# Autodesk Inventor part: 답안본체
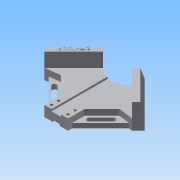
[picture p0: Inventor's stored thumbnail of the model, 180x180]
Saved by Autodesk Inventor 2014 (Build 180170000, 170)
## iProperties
Created: 2020-05
Part Number: 답안본체
Material: 알루미늄 6061
Document SubType Name: Modeling
Designer: NET
Density: 2.71 g/cm^3
Appearance: 알루미늄 - 평지
Mass: 573.609 g
Surface Area: 407.345 cm^2
Volume: 211.664 cm^3
Author: NET
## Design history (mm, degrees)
sketch "스케치1"
  geometry: L1 (0, 169.706)-(-84.853, 84.853); L2 (-84.853, 84.853)-(0, 0); L3 (0, 0)-(84.853, 84.853); L4 (84.853, 84.853)-(0, 169.706); 1 further point
  constraints: 8 end point, 3 perpendicular, 1 coincident, 1 horizontal alignment
  dimensions: "d5" = 120 distance of L3.end L1.start; "d7" = 90 deg angle of L2 L3
extrude "돌출1" new body sketch "스케치1" distance "d8" = 18; taper "d9" = 0 deg
sketch "스케치2"
  geometry: L1 (0, 169.706)-(-84.853, 84.853) reference; L2 (84.853, 84.853)-(0, 169.706) reference; L3 (0, 0)-(0, 20); L4 (-8, 20)-(8, 20); L5 (-8, 20)-(-8, 115); L6 (-8, 115)-(8, 115); L7 (8, 115)-(8, 20); L8 (0, 169.706)-(-23.241, 146.464); L9 (0, 169.706)-(35.355, 134.35); L10 (0, 169.706)-(-35.355, 134.35); L11 (35.355, 134.35)-(16.005, 115); L12 (-35.355, 134.35)-(-16.005, 115); L13 (8, 115)-(16.005, 115); L14 (16.005, 115)-(-8, 115); L15 (-8, 115)-(-16.005, 115)
  constraints: 26 end point, 5 perpendicular, 3 point on line, 2 collinear, 2 vertical, 1 midpoint, 1 parallel
  dimensions: "d11" = 20 distance of L3.end L3.start; "d13" = 16 distance of L4.start L4.end; "d14" = 95 distance of L6.end L4.end; "d15" = 50 distance of L1.start L9.end; "d16" = 50 distance of L1.start L10.end
extrude "돌출2" cut sketch "스케치2" distance "d17" = 18; taper "d18" = 0 deg
extrude "돌출3" cut sketch "스케치2" distance "d19" = 3.5; taper "d20" = 0 deg
sketch "스케치3"
  geometry: L1 (-35.355, 134.35)-(-84.853, 84.853) reference; L2 (-84.853, 84.853)-(0, 0) reference; L3 (0, 0)-(84.853, 84.853) reference; L4 (8, 20)-(-8, 20) reference; L5 (-20, 20)-(20, 20); L6 (-84.853, 84.853)-(-29.096, 29.096); L7 (-70.711, 98.995)-(-14.954, 43.238); L8 (-20, 20)-(-20, 48.284); L9 (-84.853, 84.853)-(-67.035, 102.671); L10 (-56.428, 92.064)-(-74.246, 74.246); L11 (-45.7, 81.579)-(-49.497, 77.782); L12 (-74.246, 74.246)-(-49.497, 77.782)
  constraints: 16 end point, 7 point on line, 1 collinear, 1 parallel, 1 perpendicular
  dimensions: "d21" = 40 distance of L5.start L5.end; "d22" = 20 distance between parallel lines of L6 L7; "d23" = 15 distance between parallel lines of L9 L10; "d24" = 30 distance between parallel lines of L9 L11
extrude "돌출4" cut sketch "스케치3" distance "d25" = 10; taper "d26" = 0 deg
sketch "스케치4"
  geometry: L1 (-20, 20)-(-74.246, 74.246) reference; L2 (-20, 48.284)-(-20, 20) reference; L3 (-74.246, 74.246)-(-20, 20); L4 (-70.711, 77.782)-(-20, 27.071); L5 (-65.761, 82.731)-(-22.641, 39.611); L6 (-35.355, 134.35)-(-84.853, 84.853) reference; L7 (-16.005, 115)-(16.005, 115) reference; L8 (16.005, 115)-(35.355, 134.35) reference; L9 (35.355, 134.35)-(84.853, 84.853) reference; L10 (84.853, 84.853)-(0, 0) reference; L11 (0, 0)-(-20, 20) reference; L12 (-20, 20)-(-20, 48.284) reference; L13 (-20, 48.284)-(-49.497, 77.782) reference; L14 (-49.497, 77.782)-(-74.246, 74.246) reference; L15 (-20, 20)-(-74.246, 74.246) reference; L16 (-35.355, 134.35)-(-16.005, 115) reference; L17 (-84.853, 84.853)-(-35.355, 134.35) reference; L18 (-74.246, 74.246)-(-84.853, 84.853) reference; L19 (-67.244, 102.462)-(-84.853, 84.853); L20 (-61.193, 87.299)-(-74.246, 74.246); L21 (-37.371, 78.594)-(-54.447, 61.518); L22 (-26.87, 49.497)-(-46.669, 69.296); L23 (-32.527, 43.841)-(-52.326, 63.64); L24 (-74.246, 74.246)-(-49.497, 77.782) reference; L25 (-74.246, 74.246)-(-68.059, 75.13); L26 (-20, 27.071)-(-20, 20); A1 r 4 centre (-49.497, 66.468) between (-46.669, 69.296) and (-52.326, 63.64); A2 r 4 centre (-29.698, 46.669) between (-32.527, 43.841) and (-26.87, 49.497)
  constraints: 20 end point, 11 point on line, 4 point on circle, 3 parallel, 3 perpendicular, 2 centre point, 2 collinear
  dimensions: "d27" = 5 distance between parallel lines of L1 L4; "d28" = 12 distance between parallel lines of L1 L5; "d29" = 15 distance between parallel lines of L19 L20; "d30" = 38 distance between parallel lines of L19 L21; "d31" = 4 radius of A1; "d32" = 4 radius of A2; "d33" = 28 distance of L23.start L23.end
  node "절단 모서리 투영1"
extrude "돌출5" cut sketch "스케치4" distance "d34" = 10; taper "d35" = 0 deg
extrude "돌출6" cut sketch "스케치4" distance "d36" = 10; taper "d37" = 0 deg
sketch "스케치5"
  geometry: L1 (-20, 20)-(0, 0) reference; L2 (0, 0)-(84.853, 84.853) reference; L3 (-8, 115)-(-16.005, 115) reference; L4 (-20, 20)-(20, 20); C1 r 2.25 at (-14, 26); C2 r 2.25 at (-14, 38)
  constraints: 2 centre point, 2 end point, 2 point on line, 1 equal radius, 1 parallel, 1 vertical alignment
  dimensions: "d38" = 4.5 diameter of C2; "d39" = 14 horizontal distance of L1.end C1.centre; "d40" = 40 distance of L4.start L4.end; "d43" = 6 distance from line of L4 C1.centre; "d44" = 12 distance of C2.centre C1.centre
extrude "돌출7" cut sketch "스케치5" stored distance "d41" = 10; taper "d42" = 0 deg
extrude "돌출8" cut sketch "스케치5" stored distance "d45" = 10; taper "d46" = 0 deg
sketch "스케치6"
  geometry: L1 (-16.005, 115)-(-35.355, 134.35) reference; L2 (-35.355, 134.35)-(-84.853, 84.853) reference; L3 (-84.853, 84.853)-(-74.246, 74.246) reference; L4 (-74.246, 74.246)-(-24.749, 123.744); 1 further point
  constraints: 2 end point, 2 point on line, 1 perpendicular
  dimensions: "d47" = 15 distance between parallel lines of L2 L4
extrude "돌출9" join sketch "스케치6" distance "d48" = 24; taper "d49" = 0 deg
sketch "스케치7"
  geometry: L1 (0, 0)-(-15, 0) reference; L2 (0, 42)-(0, 0) reference; L3 (-5, 0)-(0, 15); 1 further point
  constraints: 2 end point, 2 point on line
  dimensions: "d50" = 5 distance of L1.start L3.start; "d51" = 15 distance of L3.end L1.start
extrude "돌출10" cut sketch "스케치7" stored distance "d52" = 24; taper "d53" = 0 deg
sketch "스케치8"
  geometry: L1 (-20, 20)-(20, 20) reference; L2 (16.005, 115)-(-16.005, 115) reference; L3 (-6, 20)-(-6, 115); L4 (6, 115)-(6, 20); L5 (6, 115)-(-6, 115); L6 (6, 20)-(-6, 20); 3 further points
  constraints: 8 end point, 4 point on line, 2 collinear, 2 midpoint, 2 perpendicular, 1 vertical alignment
  dimensions: "d54" = 12 distance between parallel lines of L3 L4
extrude "돌출11" cut sketch "스케치8" distance "d55" = 3; taper "d56" = 0 deg
sketch "스케치9"
  geometry: C1 r 2.25 at (14, 38) reference; C2 r 2.25 at (14, 26) reference; C3 r 4 at (14, 38); C4 r 4 at (14, 26); 1 further point
  constraints: 2 centre point, 2 coincident, 1 equal radius
  dimensions: "d57" = 8 diameter of C3
extrude "돌출12" cut sketch "스케치9" distance "d58" = 10; taper "d59" = 0 deg
sketch "스케치10"
  geometry: L1 (-74.246, 74.246)-(-24.749, 123.744) reference; L2 (-24.749, 123.744)-(-31.82, 130.815) reference; 2 further points
  constraints: 1 other
  dimensions: "d60" = 35 distance from line of point (-53.033, 102.53) L2; "d61" = 5 distance from line of L1 point (-53.033, 102.53)
feature "엠보싱1" sketch "스케치10" dims "d5" = 120, "d7" = 90 deg, "d11" = 20, "d13" = 16, "d14" = 95, "d15" = 50, "d16" = 50, "d62" = 0.5, "d63" = 0
fillet "모깎기1" dims "d64" = 5
node "솔리드1"
mirror "대칭1"
mirror "대칭2"
mirror "대칭3"
